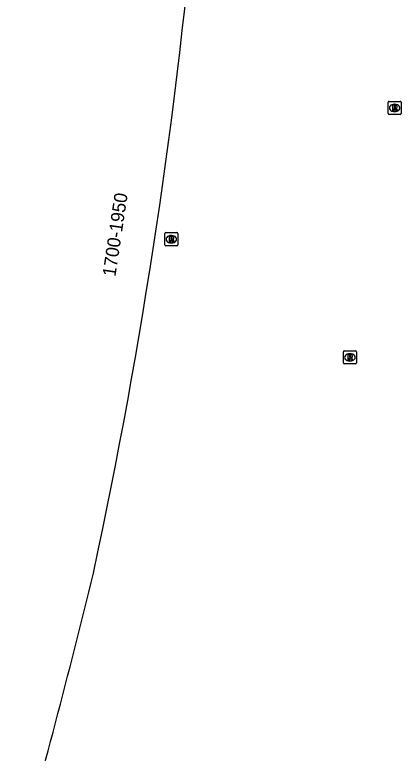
# Model space of a CAD drawing. Extents: x 155018 to 156648, y 383980 to 385733.
# Drawn here: x 155957.9 to 155987.3, y 384509 to 384565.1 of the extents above; entities that cross this region are included whole.
import ezdxf

# ---------------------------------------------------------------- set-up
doc = ezdxf.new("R2010")
doc.units = 0
for name, color, linetype in [('IMGEO_Pand', 7, 'Continuous'), ('IMGEO_Pand_nummerreeks', 7, 'Continuous'), ('IMGEO_Rioolput', 7, 'Continuous')]:
    doc.layers.add(name, color=color, linetype=linetype)

msp = doc.modelspace()

# ---------------------------------------------------------------- linework, layer by layer
at = {"layer": 'IMGEO_Pand'}
for centre, radius, start, end in [((155548.879, 384611.802), 424.474, 347.88019, 355.10015), ((155360.444, 384669.445), 621.039, 344.166628, 346.330579)]:
    msp.add_arc(centre, radius, start, end, dxfattribs=at)
at = {"layer": 'IMGEO_Rioolput'}
for p, q in [((155986.263, 384557.599), (155986.263, 384558.451)), ((155986.338, 384558.525), (155987.19, 384558.525)), ((155986.751, 384558.305), (155986.776, 384558.305)), ((155987.264, 384558.451), (155987.264, 384557.599)), ((155986.774, 384557.745), (155986.749, 384557.745)), ((155987.19, 384557.525), (155986.338, 384557.525)), ((155969.307, 384547.628), (155969.307, 384548.48)), ((155969.382, 384548.554), (155970.234, 384548.554)), ((155969.795, 384548.334), (155969.82, 384548.334)), ((155970.308, 384548.48), (155970.308, 384547.628)), ((155969.818, 384547.774), (155969.793, 384547.774)), ((155970.234, 384547.554), (155969.382, 384547.554)), ((155982.869, 384538.654), (155982.869, 384539.506)), ((155982.944, 384539.58), (155983.796, 384539.58)), ((155983.357, 384539.36), (155983.382, 384539.36)), ((155983.87, 384539.506), (155983.87, 384538.654)), ((155983.38, 384538.8), (155983.355, 384538.8)), ((155983.796, 384538.58), (155982.944, 384538.58))]:
    msp.add_line(p, q, dxfattribs=at)
for points in [[(155986.263, 384557.599), (155986.263, 384558.451)], [(155986.338, 384558.525), (155987.19, 384558.525)], [(155987.264, 384558.451), (155987.264, 384557.599)], [(155986.852, 384558.223), (155986.6, 384558.225), (155986.6, 384557.825)], [(155986.6, 384557.825), (155986.724, 384557.825), (155986.724, 384557.987), (155986.735, 384557.987)], [(155986.778, 384558.144), (155986.724, 384558.144), (155986.724, 384558.063)], [(155986.724, 384558.063), (155986.776, 384558.063)], [(155986.782, 384557.958), (155986.853, 384557.825), (155986.993, 384557.825), (155986.928, 384557.951)], [(155987.19, 384557.525), (155986.338, 384557.525)], [(155969.307, 384547.628), (155969.307, 384548.48)], [(155969.382, 384548.554), (155970.234, 384548.554)], [(155969.896, 384548.252), (155969.644, 384548.254), (155969.644, 384547.854)], [(155970.308, 384548.48), (155970.308, 384547.628)], [(155969.644, 384547.854), (155969.768, 384547.854), (155969.768, 384548.016), (155969.779, 384548.016)], [(155969.822, 384548.173), (155969.768, 384548.173), (155969.768, 384548.092)], [(155969.768, 384548.092), (155969.82, 384548.092)], [(155969.826, 384547.987), (155969.897, 384547.854), (155970.037, 384547.854), (155969.972, 384547.98)], [(155970.234, 384547.554), (155969.382, 384547.554)], [(155982.869, 384538.654), (155982.869, 384539.506)], [(155982.944, 384539.58), (155983.796, 384539.58)], [(155983.458, 384539.278), (155983.206, 384539.28), (155983.206, 384538.88)], [(155983.87, 384539.506), (155983.87, 384538.654)], [(155983.206, 384538.88), (155983.33, 384538.88), (155983.33, 384539.042), (155983.341, 384539.042)], [(155983.384, 384539.199), (155983.33, 384539.199), (155983.33, 384539.118)], [(155983.33, 384539.118), (155983.382, 384539.118)], [(155983.388, 384539.013), (155983.459, 384538.88), (155983.599, 384538.88), (155983.534, 384539.006)], [(155983.796, 384538.58), (155982.944, 384538.58)]]:
    msp.add_lwpolyline(points, dxfattribs=at)
for centre, radius, start, end in [((155986.34, 384558.449), 0.0765, 91.552, 178.448), ((155986.34, 384558.449), 0.0765, 91.552, 178.448), ((155987.188, 384558.449), 0.0765, 1.552, 88.448), ((155987.188, 384558.449), 0.0765, 1.552, 88.448), ((155986.734, 384557.934), 0.0533, 26.0293, 88.6989), ((155986.76, 384558.252), 0.19, 274.7715, 282.9687), ((155986.784, 384558.048), 0.0964, 77.0061, 93.1865), ((155986.798, 384558.105), 0.0378, 276.6634, 79.6772), ((155986.851, 384558.113), 0.109, 350.3612, 89.416), ((155986.849, 384558.113), 0.112, 277.5842, 350.9817), ((155986.833, 384557.898), 0.108, 29.5134, 73.7905), ((155986.34, 384557.601), 0.0765, 181.552, 268.448), ((155986.34, 384557.601), 0.0765, 181.552, 268.448), ((155987.188, 384557.601), 0.0765, 271.552, 358.448), ((155987.188, 384557.601), 0.0765, 271.552, 358.448), ((155969.384, 384548.478), 0.0765, 91.552, 178.448), ((155969.384, 384548.478), 0.0765, 91.552, 178.448), ((155969.895, 384548.142), 0.109, 350.3612, 89.416), ((155970.232, 384548.478), 0.0765, 1.552, 88.448), ((155970.232, 384548.478), 0.0765, 1.552, 88.448), ((155969.384, 384547.63), 0.0765, 181.552, 268.448), ((155969.384, 384547.63), 0.0765, 181.552, 268.448), ((155969.778, 384547.963), 0.0533, 26.0293, 88.6989), ((155969.804, 384548.281), 0.19, 274.7715, 282.9687), ((155969.828, 384548.077), 0.0964, 77.0061, 93.1865), ((155969.842, 384548.134), 0.0378, 276.6634, 79.6772), ((155969.893, 384548.142), 0.112, 277.5842, 350.9817), ((155969.877, 384547.927), 0.108, 29.5134, 73.7905), ((155970.232, 384547.63), 0.0765, 271.552, 358.448), ((155970.232, 384547.63), 0.0765, 271.552, 358.448), ((155982.946, 384539.504), 0.0765, 91.552, 178.448), ((155982.946, 384539.504), 0.0765, 91.552, 178.448), ((155983.457, 384539.168), 0.109, 350.3612, 89.416), ((155983.794, 384539.504), 0.0765, 1.552, 88.448), ((155983.794, 384539.504), 0.0765, 1.552, 88.448), ((155982.946, 384538.656), 0.0765, 181.552, 268.448), ((155982.946, 384538.656), 0.0765, 181.552, 268.448), ((155983.34, 384538.989), 0.0533, 26.0293, 88.6989), ((155983.366, 384539.307), 0.19, 274.7715, 282.9687), ((155983.39, 384539.103), 0.0964, 77.0061, 93.1865), ((155983.404, 384539.16), 0.0378, 276.6634, 79.6772), ((155983.455, 384539.168), 0.112, 277.5842, 350.9817), ((155983.439, 384538.953), 0.108, 29.5134, 73.7905), ((155983.794, 384538.656), 0.0765, 271.552, 358.448), ((155983.794, 384538.656), 0.0765, 271.552, 358.448)]:
    msp.add_arc(centre, radius, start, end, dxfattribs=at)
for centre, major_axis, ratio, start_param, end_param in [((155986.75, 384558.025), (-0.387, 0.002), 0.722429, 4.712389, 7.853982), ((155986.775, 384558.025), (-0.39, 0.002), 0.717154, 1.570796, 4.712389), ((155969.794, 384548.054), (-0.387, 0.002), 0.722429, 4.712389, 7.853982), ((155969.819, 384548.054), (-0.39, 0.002), 0.717154, 1.570796, 4.712389), ((155983.356, 384539.08), (-0.387, 0.002), 0.722429, 4.712389, 7.853982), ((155983.381, 384539.08), (-0.39, 0.002), 0.717154, 1.570796, 4.712389)]:
    msp.add_ellipse(centre, major_axis=major_axis, ratio=ratio, start_param=start_param, end_param=end_param, dxfattribs=at)

# ---------------------------------------------------------------- texts
at = {"layer": 'IMGEO_Pand_nummerreeks'}
msp.add_text('1700-1950', height=1, rotation=81.5032, dxfattribs=at).set_placement((155965.558, 384545.168))

doc.saveas('drawing.dxf')
